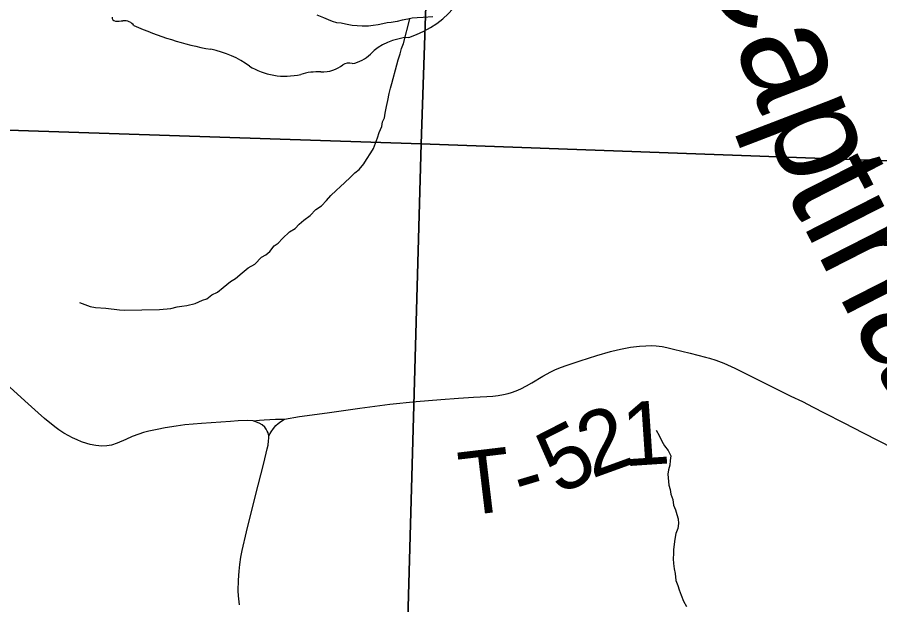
# Model space of a CAD drawing. Extents: x -3.3 to 34, y 0 to 56.8.
# Drawn here: x -1.696 to -0.926, y 31.3 to 31.825 of the extents above; entities that cross this region are included whole.
import ezdxf

# ---------------------------------------------------------------- set-up
doc = ezdxf.new("R2010")
doc.units = 0
for name, color, linetype in [('GM_X_Corporation', 7, 'Continuous'), ('GM_X_Major_River', 7, 'Continuous'), ('GM_X_Major_River_Text', 7, 'Continuous'), ('GM_X_State_Route', 7, 'Continuous'), ('GM_X_State_Shield', 7, 'Continuous'), ('GM_X_Township_Road', 7, 'Continuous'), ('GM_X_Township_Road_Text', 7, 'Continuous'), ('GT_Project_Soil_Layers', 7, 'Continuous')]:
    doc.layers.add(name, color=color, linetype=linetype)

msp = doc.modelspace()

# ---------------------------------------------------------------- linework, layer by layer
at = {"layer": 'GM_X_Corporation'}
for points in [[(-2.31978, 32.74649), (-1.30168, 32.71458), (-1.33537, 31.71163), (-2.35994, 31.74572)], [(-1.30168, 32.71458), (-0.28775, 32.6826), (-0.3225, 31.67471), (-1.33537, 31.71163)], [(-1.33537, 31.71163), (-1.36367, 30.70347), (-2.39277, 30.73672), (-2.35994, 31.74572)], [(-1.33537, 31.71163), (-0.3225, 31.67471), (-0.36109, 30.66979), (-1.36367, 30.70347)]]:
    msp.add_lwpolyline(points, close=True, dxfattribs=at)
at = {"layer": 'GM_X_Major_River'}
msp.add_lwpolyline([(-1.32502, 31.82519), (-1.33373, 31.82431), (-1.33904, 31.82424), (-1.34358, 31.8238), (-1.34736, 31.82298), (-1.35228, 31.82215), (-1.35682, 31.82095), (-1.36211, 31.82012), (-1.3659, 31.81968), (-1.36968, 31.81887), (-1.37384, 31.81805), (-1.37838, 31.81723), (-1.38254, 31.81679), (-1.38823, 31.81671), (-1.39696, 31.81735), (-1.40304, 31.8184), (-1.40685, 31.81949), (-1.41065, 31.81982), (-1.41445, 31.8209), (-1.41826, 31.82237), (-1.42246, 31.82421), (-1.42818, 31.8264)], dxfattribs=at)
at = {"layer": 'GM_X_State_Route'}
msp.add_lwpolyline([(-1.49756, 31.30005), (-1.49848, 31.30812), (-1.49871, 31.31255), (-1.49856, 31.32192), (-1.49795, 31.33017), (-1.49726, 31.33612), (-1.49634, 31.34253), (-1.49511, 31.34852), (-1.49137, 31.3652), (-1.48351, 31.39646), (-1.47598, 31.42643), (-1.47278, 31.43926), (-1.47212, 31.44271), (-1.47165, 31.4464), (-1.47146, 31.44879), (-1.47151, 31.45099), (-1.47212, 31.45356), (-1.47283, 31.45509), (-1.47384, 31.45685), (-1.475, 31.45858), (-1.47722, 31.46071), (-1.48001, 31.4622), (-1.48548, 31.46434), (-1.49061, 31.46457), (-1.49892, 31.46424), (-1.50548, 31.46381), (-1.53164, 31.46202), (-1.54635, 31.46063), (-1.55416, 31.45964), (-1.56402, 31.458), (-1.57101, 31.45668), (-1.57861, 31.45497), (-1.58334, 31.4538), (-1.58737, 31.45249), (-1.59337, 31.45019), (-1.59902, 31.44758), (-1.60677, 31.44435), (-1.61186, 31.44271), (-1.61604, 31.44195), (-1.62032, 31.44181), (-1.62566, 31.44222), (-1.63088, 31.44319), (-1.6339, 31.4441), (-1.63866, 31.44567), (-1.64244, 31.44723), (-1.64663, 31.44904), (-1.65001, 31.45093), (-1.65445, 31.45329), (-1.65888, 31.45625), (-1.66244, 31.45884), (-1.67169, 31.46652), (-1.67712, 31.47132), (-1.68927, 31.48207), (-1.7026, 31.4945)], dxfattribs=at)
at = {"layer": 'GM_X_State_Shield'}
for centre, major_axis, start_param, end_param in [((-1.37961, 31.8714), (0.08742, 0), 5.101752, 6.440018), ((-1.60756, 31.82425), (0.00385, 0), 3.00124, 4.508301), ((-1.60698, 31.84472), (0.0294, 0), 4.665946, 4.897461), ((-1.60097, 31.81314), (0.0106, 0), 0.519207, 1.627899), ((-1.46714, 31.99294), (0.2524, 0), 4.195997, 4.488961), ((-1.34275, 31.76851), (0.04788, 0), 1.647645, 2.488434), ((-1.54239, 31.73478), (0.07897, 0), 0.823519, 1.323587), ((-1.40342, 31.80529), (0.02824, 0), 4.937069, 5.64225), ((-1.42436, 31.79716), (0.0267, 0), 4.691044, 5.507374), ((-1.40021, 31.77778), (0.00752, 0), 1.147584, 2.315152), ((-1.45698, 31.81215), (0.05011, 0), 4.026481, 4.996735), ((-1.42802, 31.74296), (0.04118, 0), 1.495662, 1.94098)]:
    msp.add_ellipse(centre, major_axis=major_axis, ratio=0.8, start_param=start_param, end_param=end_param, dxfattribs=at)
at = {"layer": 'GM_X_Township_Road'}
for points in [[(-1.48548, 31.46434), (-1.47973, 31.4649), (-1.47546, 31.46523), (-1.46543, 31.46564), (-1.45735, 31.46587), (-1.44398, 31.46803), (-1.4194, 31.47156), (-1.39022, 31.47567), (-1.36358, 31.4792), (-1.33999, 31.48167), (-1.31796, 31.4834), (-1.30226, 31.48455), (-1.28878, 31.48545), (-1.27692, 31.48603), (-1.27141, 31.48633), (-1.26675, 31.4869), (-1.26212, 31.48775), (-1.25776, 31.48882), (-1.2549, 31.48967), (-1.25055, 31.4912), (-1.24657, 31.49283), (-1.24159, 31.49548), (-1.23667, 31.49827), (-1.22697, 31.50403), (-1.21965, 31.50814), (-1.21611, 31.50995), (-1.21274, 31.51135), (-1.20699, 31.51349), (-1.19362, 31.51785), (-1.1787, 31.52271), (-1.16638, 31.52614), (-1.16018, 31.52772), (-1.15595, 31.52866), (-1.14856, 31.52997), (-1.14071, 31.53093), (-1.13493, 31.53136), (-1.12967, 31.53144), (-1.12572, 31.53124), (-1.12048, 31.53064), (-1.11637, 31.52988), (-1.11014, 31.52832), (-1.09536, 31.5246), (-1.08163, 31.52113), (-1.07829, 31.52024), (-1.07263, 31.51846), (-1.06534, 31.5157), (-1.05565, 31.5113), (-1.03758, 31.50249), (-1.02341, 31.49536), (-1.00559, 31.48639), (-0.9953, 31.48142), (-0.98558, 31.47648), (-0.97592, 31.47156), (-0.95813, 31.46242), (-0.9409, 31.45356), (-0.91435, 31.43992)], [(-1.47151, 31.45099), (-1.46921, 31.45454), (-1.46726, 31.45749), (-1.46519, 31.46005), (-1.46311, 31.46191), (-1.46058, 31.46383), (-1.45735, 31.46587)]]:
    msp.add_lwpolyline(points, dxfattribs=at)
at = {"layer": 'GT_Project_Soil_Layers'}
for points in [[(-1.64044, 31.56982), (-1.63092, 31.56653), (-1.62598, 31.56546), (-1.61687, 31.56483), (-1.60471, 31.56348), (-1.60054, 31.56316), (-1.56907, 31.5636), (-1.55885, 31.56451), (-1.55318, 31.5661), (-1.54902, 31.56654), (-1.54448, 31.56737), (-1.53729, 31.56899), (-1.53051, 31.57212), (-1.52673, 31.57331), (-1.52223, 31.57679), (-1.51734, 31.57914), (-1.51208, 31.58339), (-1.50571, 31.58879), (-1.5012, 31.59151), (-1.4952, 31.59653), (-1.48995, 31.60078), (-1.48393, 31.60428), (-1.47795, 31.61044), (-1.47418, 31.61239), (-1.47043, 31.61548), (-1.4667, 31.62047), (-1.46295, 31.6228), (-1.45921, 31.62703), (-1.45285, 31.63319), (-1.44796, 31.63592), (-1.44422, 31.63977), (-1.4401, 31.64362), (-1.43446, 31.6475), (-1.42961, 31.65288), (-1.42435, 31.65637), (-1.41986, 31.66099), (-1.41613, 31.6656), (-1.41126, 31.66984), (-1.40752, 31.67369), (-1.40377, 31.67678), (-1.39853, 31.68179), (-1.39479, 31.68564), (-1.39066, 31.68873), (-1.38656, 31.69373), (-1.38433, 31.69756), (-1.38025, 31.70369), (-1.37802, 31.70751), (-1.37619, 31.7121), (-1.37436, 31.71706), (-1.37291, 31.72163), (-1.3707, 31.72698), (-1.37, 31.73117), (-1.36816, 31.73499), (-1.36746, 31.73917), (-1.3664, 31.74488), (-1.36533, 31.75021), (-1.3639, 31.75669), (-1.36283, 31.76126), (-1.36175, 31.76545), (-1.35705, 31.78222), (-1.35597, 31.78679), (-1.35415, 31.79213), (-1.35307, 31.79671), (-1.35124, 31.80129), (-1.34569, 31.82334)], [(-1.12585, 31.45595), (-1.12313, 31.45105), (-1.12078, 31.44615), (-1.11845, 31.44201), (-1.11499, 31.43788), (-1.11264, 31.43298), (-1.11334, 31.42879), (-1.11367, 31.42461), (-1.11475, 31.42042), (-1.11545, 31.41662), (-1.11456, 31.40676), (-1.11338, 31.40298), (-1.11256, 31.39882), (-1.11097, 31.39391), (-1.11015, 31.38898), (-1.10858, 31.38483), (-1.10738, 31.38067), (-1.10619, 31.37689), (-1.10576, 31.37272), (-1.10645, 31.36816), (-1.10829, 31.36358), (-1.10898, 31.35863), (-1.11037, 31.3495), (-1.11032, 31.34571), (-1.11064, 31.34115), (-1.1102, 31.33698), (-1.10976, 31.33205), (-1.10894, 31.32789), (-1.1081, 31.32183), (-1.10652, 31.31729), (-1.10534, 31.31351), (-1.10337, 31.30861), (-1.1014, 31.30332), (-1.09868, 31.29843)]]:
    msp.add_lwpolyline(points, dxfattribs=at)

# ---------------------------------------------------------------- texts
at = {"layer": 'GM_X_Major_River_Text'}
for s, height, rotation, p in [('Cap', 0.094717, 291.0013, (-1.08941, 31.88761)), ('tina', 0.094703, 297.00242, (-1.01174, 31.67189))]:
    msp.add_text(s, height=height, rotation=rotation, dxfattribs=at).set_placement(p)
at = {"layer": 'GM_X_Township_Road_Text'}
for s, rotation, p in [('1', 3.82792, (-1.15444, 31.42362)), ('2', 19.95243, (-1.18321, 31.41255)), ('5', 27.08367, (-1.21266, 31.39736)), ('T', 6.80448, (-1.29808, 31.37927)), ('-', 16.67807, (-1.24544, 31.38647))]:
    msp.add_text(s, height=0.05682, rotation=rotation, dxfattribs=at).set_placement(p)

doc.saveas('drawing.dxf')
